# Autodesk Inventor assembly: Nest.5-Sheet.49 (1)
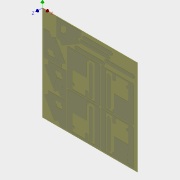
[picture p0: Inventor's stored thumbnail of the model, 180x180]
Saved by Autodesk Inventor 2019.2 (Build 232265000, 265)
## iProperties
Created: 2019-02
Part Number: Nest.5-Sheet.49 (1)
Document SubType Name: Assembly
Designer: User
Author: User
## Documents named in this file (5)
- D:\Slotmachine\Workspaces\Workspace\Cabinet\Hopper\Nest.5-Sheet.49 (1).iam
- D:\Slotmachine\Workspaces\Workspace\Cabinet\Hopper\CAM parts\STOCK Aluminum 6061_Sheet.49 (1).ipt
- D:\Slotmachine\Workspaces\Workspace\Cabinet\Hopper\CAM parts\Hopper - Frame Right_2D.ipt
- D:\Slotmachine\Workspaces\Workspace\Cabinet\Hopper\CAM parts\Hopper - Handle_2D.ipt
- D:\Slotmachine\Workspaces\Workspace\Cabinet\Hopper\CAM parts\Hopper - Base Plate_2D.ipt
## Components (17 placed, 4 different names)
1. STOCK Aluminum 6061:1
2. Hopper - Frame Right_2D:1
3. Hopper - Frame Right_2D:2
4. Hopper - Frame Right_2D:3
5. Hopper - Frame Right_2D:4
6. Hopper - Base Plate_2D:1
7. Hopper - Base Plate_2D:2
8. Hopper - Base Plate_2D:3
9. Hopper - Base Plate_2D:4
10. Hopper - Handle_2D:1
11. Hopper - Handle_2D:2
12. Hopper - Handle_2D:3
13. Hopper - Handle_2D:4
14. Hopper - Handle_2D:5
15. Hopper - Handle_2D:6
16. Hopper - Handle_2D:7
17. Hopper - Handle_2D:8
